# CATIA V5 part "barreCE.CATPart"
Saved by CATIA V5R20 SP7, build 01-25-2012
Part number: barreCE
Publications: "pivot_CE_AB", "pivot_CE_CD", "pivot_CE_EF", "Plan_Ref"
Bounding box of the stored display mesh (mm): x 19 to 23, y 173.248 to 717.209, z 140.784 to 277.799
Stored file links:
  G:\IAO\apres\barreCE.CATPart
  G:\IAO\apres\psedsuay.CATProduct
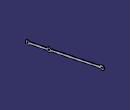
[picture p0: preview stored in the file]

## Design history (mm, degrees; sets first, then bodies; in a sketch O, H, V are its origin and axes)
External parameters (linked from other documents)
  External.Longueur_AB = 100 mm
  External.Epaisseur = 4 mm
  External.Diametre = 30 mm
  External.Largeur = 15 mm
  External.Diametre_pivot = 10 mm
Set1
  Point1 "Point_C": linked copy from another document
  Point2 "Point_E": linked copy from another document
  Point3 "Point_B": linked copy from another document
  Plane1 "Plan_Ref": linked copy from another document
Set2 "skelette"
  Line1 "Barre_CE": type PtPt, FirstPoint Point1, SecondPoint Point2
  Line2 "pivot_CE_AB": type Normal, RefPoint Point3, RefSkin Plane1, Start -20, End 20
  Line3 "pivot_CE_CD": type Normal, RefPoint Point1, RefSkin Plane1, Start -20, End 20
  Line4 "pivot_CE_EF": type Normal, RefPoint Point2, RefSkin Plane1, Start -20, End 20
Set3 "piece"
  Plane2: type OffsetPt, RefPlane yz-plane, RefPoint Point3
  Plane3: type Offset, RefPlane Plane2, Offset 19 {= 0.15*External.Longueur_AB +External.Epaisseur}
  Sketch1 on Plane3, origin (19, 0, 0), H (0, 1, 0), V (0, 0, 1)
    arc A1 centre (188.2401, 155.7819) radius 15 from (199.4289, 165.7725) to (202.4866, 151.0874) ccw
    arc A2 centre (702.2166, 262.8015) radius 15 from (691.0278, 252.8109) to (687.9701, 267.4959) ccw
    arc A3 centre (335.0906, 186.3589) radius 15 from (346.2793, 196.3495) to (320.8441, 191.0534) ccw
    point P3 (335.0906, 186.3589)
    construction line L1 (188.2401, 155.7819) -> (702.2166, 262.8015)
    reference projected point E1 (335.0906, 186.3589) from Line2
    reference projected point E2 (702.2166, 262.8015) from Line3
    reference projected point E3 (188.2401, 155.7819) from Line4
    line L2 (202.4866, 151.0874) -> (323.9018, 176.3683)
    line L3 (687.9701, 267.4959) -> (346.2793, 196.3495)
    point P8 (349.337, 181.6644)
    line L4 (320.8441, 191.0534) -> (199.4289, 165.7725)
    point P11 (323.9018, 176.3683)
    line L5 (349.337, 181.6644) -> (691.0278, 252.8109)
    arc A4 centre (335.0906, 186.3589) radius 15 from (323.9018, 176.3683) to (349.337, 181.6644) ccw
    radius A2 = 15 {= External.Diametre /2}
    radius A3 = 15 {= External.Diametre /2}
    radius A1 = 15 {= External.Diametre /2}
    distance L2 L3 = 15 {= External.Largeur}
    coincidence: P3 L1, L2 P8, L3 L4, A3 P11, L2 L5, A3 A4
    concentricity: A3 E1, A2 E2, A1 E3
    parallelism: L2 L1, L3 L1
    symmetry: L2 L3 L1
Body1 (main body)
  Pad1: profile Sketch1, direction (1, 0, 0), length 4 {= External.Epaisseur}
  Sketch2 on Plane3, origin (19, 335.0906, 186.3589), H (0, 1, 0), V (0, 0, 1)
    point P1 (0, 0)
  Hole1: placed by Sketch2, at (19, 335.0906, 186.3589) direction (1, 0, 0), diameter 10 {= External.Diametre_pivot}, through (limit type 3)
  Sketch3 on Plane3, origin (19, 335.0906, 186.3589), H (0, 1, 0), V (0, 0, 1)
    point P1 (-146.8504, -30.577)
    reference projected point E1 (-146.8504, -30.577) from Line4
    coincidence: P1 E1
  Hole2: placed by Sketch3, at (19, 188.2401, 155.7819) direction (1, 0, 0), diameter 10 {= External.Diametre_pivot}, depth 10
  Sketch4 on Plane3, origin (19, 335.0906, 186.3589), H (0, 1, 0), V (0, 0, 1)
    point P1 (367.1261, 76.4425)
    reference projected point E1 (367.1261, 76.4425) from Line3
    coincidence: P1 E1
  Hole3: placed by Sketch4, at (19, 702.2166, 262.8015) direction (1, 0, 0), diameter 10 {= External.Diametre_pivot}, depth 10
